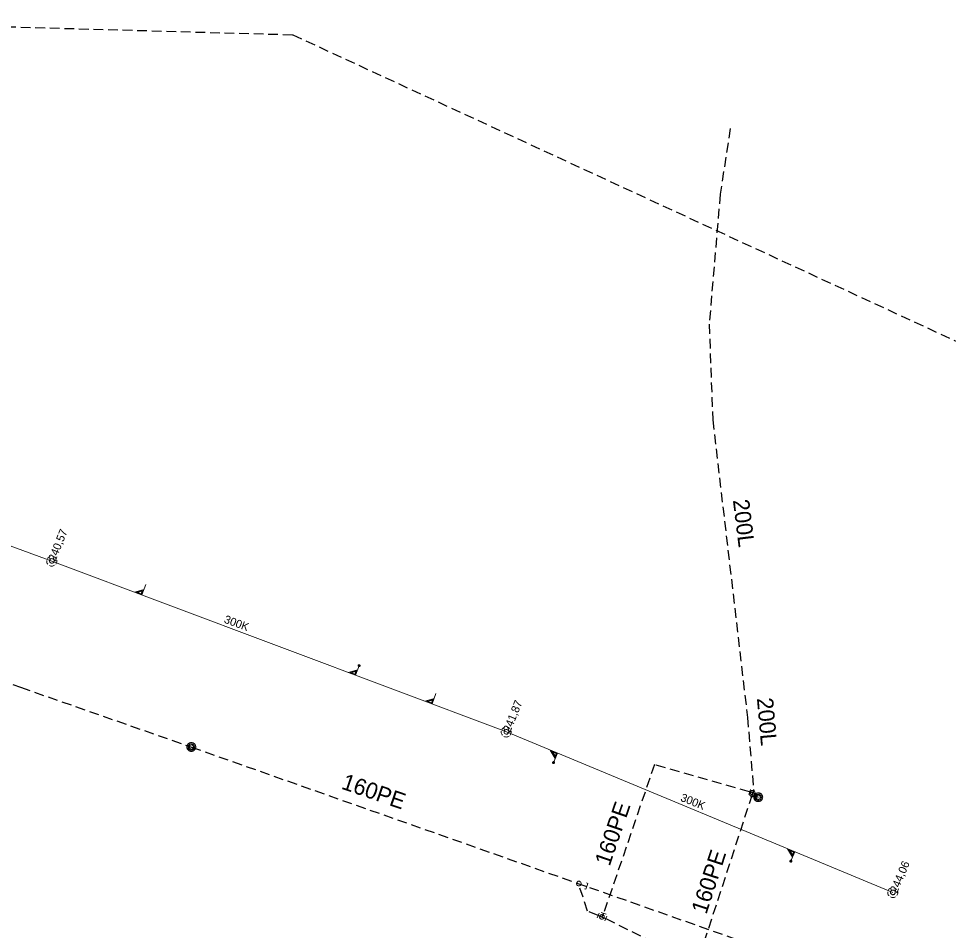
# Model space of a CAD drawing. Extents: x -735085 to -733500, y -1044153 to -1043402.
# Drawn here: x -734984.7 to -734892.7, y -1043524 to -1043433.9 of the extents above; entities that cross this region are included whole.
import ezdxf

# ---------------------------------------------------------------- set-up
doc = ezdxf.new("R2010")
doc.units = 0
doc.header["$LTSCALE"] = 0.32
doc.linetypes.add('MEDIUM_DASHED', pattern=[4.5, 3, -1.5])
doc.layers.add('15', color=7, linetype='Continuous')
doc.layers.add('16', color=7, linetype='Continuous')
for name, color, linetype, lineweight in [('18', 7, 'Continuous', 13), ('20', 7, 'Continuous', 13), ('63', 7, 'MEDIUM_DASHED', 25), ('8', 7, 'Continuous', 13)]:
    doc.layers.add(name, color=color, linetype=linetype, lineweight=lineweight)

msp = doc.modelspace()

# ---------------------------------------------------------------- linework, layer by layer
at = {"layer": '18'}
for points in [[(-734981.868, -1043487.429), (-734981.874, -1043487.506), (-734981.869, -1043487.583), (-734981.852, -1043487.658), (-734981.823, -1043487.729), (-734981.782, -1043487.795), (-734981.767, -1043487.817)], [(-734981.523, -1043487.037), (-734981.594, -1043487.065), (-734981.661, -1043487.104), (-734981.721, -1043487.152), (-734981.772, -1043487.209), (-734981.796, -1043487.243)], [(-734980.982, -1043487.22), (-734981.032, -1043487.162), (-734981.09, -1043487.112), (-734981.155, -1043487.071), (-734981.226, -1043487.042), (-734981.275, -1043487.028)], [(-734980.987, -1043487.806), (-734980.946, -1043487.741), (-734980.915, -1043487.671), (-734980.896, -1043487.596), (-734980.888, -1043487.52), (-734980.893, -1043487.443), (-734980.899, -1043487.408)], [(-734981.61, -1043487.946), (-734981.54, -1043487.977), (-734981.465, -1043487.996), (-734981.389, -1043488.003), (-734981.312, -1043487.998), (-734981.237, -1043487.981), (-734981.165, -1043487.953), (-734981.105, -1043487.918)], [(-734972.091, -1043489.814), (-734972.477, -1043490.84), (-734973.197, -1043490.569), (-734972.273, -1043490.299)], [(-734972.362, -1043490.392), (-734972.508, -1043490.781), (-734973.038, -1043490.582), (-734972.361, -1043490.391)], [(-734972.435, -1043490.454), (-734972.538, -1043490.726), (-734972.886, -1043490.595), (-734972.434, -1043490.454)], [(-734950.962, -1043497.749), (-734951.347, -1043498.774), (-734952.068, -1043498.503), (-734951.144, -1043498.233)], [(-734951.306, -1043498.388), (-734951.408, -1043498.661), (-734951.756, -1043498.53), (-734951.305, -1043498.388)], [(-734943.401, -1043500.593), (-734943.787, -1043501.619), (-734944.507, -1043501.348), (-734943.583, -1043501.078)], [(-734943.672, -1043501.171), (-734943.818, -1043501.56), (-734944.348, -1043501.361), (-734943.671, -1043501.17)], [(-734943.745, -1043501.233), (-734943.848, -1043501.505), (-734944.196, -1043501.374), (-734943.744, -1043501.233)], [(-734936.593, -1043503.917), (-734936.664, -1043503.945), (-734936.73, -1043503.984), (-734936.791, -1043504.032), (-734936.842, -1043504.089), (-734936.865, -1043504.123)], [(-734936.051, -1043504.1), (-734936.102, -1043504.042), (-734936.159, -1043503.992), (-734936.225, -1043503.951), (-734936.296, -1043503.922), (-734936.345, -1043503.908)], [(-734936.938, -1043504.309), (-734936.943, -1043504.386), (-734936.938, -1043504.463), (-734936.921, -1043504.538), (-734936.892, -1043504.609), (-734936.852, -1043504.675), (-734936.837, -1043504.697)], [(-734936.679, -1043504.826), (-734936.61, -1043504.857), (-734936.534, -1043504.876), (-734936.458, -1043504.883), (-734936.382, -1043504.878), (-734936.306, -1043504.861), (-734936.235, -1043504.833), (-734936.174, -1043504.798)], [(-734936.056, -1043504.686), (-734936.016, -1043504.621), (-734935.985, -1043504.551), (-734935.965, -1043504.476), (-734935.958, -1043504.4), (-734935.963, -1043504.323), (-734935.968, -1043504.288)], [(-734931.808, -1043507.489), (-734931.388, -1043506.478), (-734932.1, -1043506.182), (-734931.61, -1043507.011)], [(-734931.611, -1043506.882), (-734931.452, -1043506.498), (-734931.974, -1043506.281), (-734931.612, -1043506.884)], [(-734931.623, -1043506.787), (-734931.511, -1043506.518), (-734931.853, -1043506.375), (-734931.622, -1043506.788)], [(-734908.348, -1043517.226), (-734907.928, -1043516.215), (-734908.64, -1043515.919), (-734908.15, -1043516.748)], [(-734908.151, -1043516.619), (-734907.992, -1043516.235), (-734908.514, -1043516.018), (-734908.152, -1043516.621)], [(-734908.163, -1043516.524), (-734908.051, -1043516.255), (-734908.393, -1043516.112), (-734908.162, -1043516.525)], [(-734898.728, -1043520.169), (-734898.733, -1043520.246), (-734898.728, -1043520.323), (-734898.712, -1043520.398), (-734898.683, -1043520.469), (-734898.642, -1043520.535), (-734898.627, -1043520.557)], [(-734898.383, -1043519.777), (-734898.454, -1043519.805), (-734898.521, -1043519.844), (-734898.581, -1043519.892), (-734898.632, -1043519.949), (-734898.656, -1043519.983)], [(-734898.47, -1043520.686), (-734898.4, -1043520.717), (-734898.325, -1043520.736), (-734898.249, -1043520.743), (-734898.172, -1043520.738), (-734898.097, -1043520.721), (-734898.025, -1043520.693), (-734897.965, -1043520.658)], [(-734897.842, -1043519.96), (-734897.892, -1043519.902), (-734897.95, -1043519.852), (-734898.015, -1043519.811), (-734898.086, -1043519.782), (-734898.135, -1043519.768)], [(-734897.847, -1043520.546), (-734897.806, -1043520.481), (-734897.775, -1043520.411), (-734897.755, -1043520.336), (-734897.748, -1043520.26), (-734897.753, -1043520.183), (-734897.759, -1043520.148)]]:
    msp.add_lwpolyline(points, dxfattribs=at)
for points in [[(-734981.139, -1043487.489), (-734981.145, -1043487.437), (-734981.163, -1043487.387), (-734981.191, -1043487.343), (-734981.229, -1043487.306), (-734981.274, -1043487.279), (-734981.324, -1043487.263), (-734981.376, -1043487.258), (-734981.428, -1043487.265), (-734981.477, -1043487.284), (-734981.521, -1043487.314), (-734981.556, -1043487.353), (-734981.582, -1043487.398), (-734981.597, -1043487.449), (-734981.6, -1043487.501), (-734981.592, -1043487.553), (-734981.571, -1043487.601), (-734981.541, -1043487.644), (-734981.501, -1043487.679), (-734981.455, -1043487.703), (-734981.404, -1043487.717), (-734981.352, -1043487.719), (-734981.3, -1043487.709), (-734981.252, -1043487.687), (-734981.21, -1043487.655), (-734981.177, -1043487.615), (-734981.153, -1043487.568), (-734981.141, -1043487.517)], [(-734951.232, -1043498.325), (-734951.378, -1043498.715), (-734951.908, -1043498.516)], [(-734951.083, -1043497.804), (-734951.089, -1043497.837), (-734951.083, -1043497.87), (-734951.066, -1043497.898), (-734951.04, -1043497.919), (-734951.009, -1043497.93), (-734950.975, -1043497.928), (-734950.943, -1043497.916), (-734950.919, -1043497.893), (-734950.904, -1043497.863), (-734950.901, -1043497.83), (-734950.909, -1043497.797), (-734950.928, -1043497.77), (-734950.955, -1043497.751), (-734950.988, -1043497.742), (-734951.022, -1043497.745), (-734951.051, -1043497.761), (-734951.074, -1043497.786)], [(-734951.058, -1043497.814), (-734951.062, -1043497.842), (-734951.055, -1043497.869), (-734951.037, -1043497.89), (-734951.011, -1043497.903), (-734950.983, -1043497.904), (-734950.957, -1043497.892), (-734950.938, -1043497.872), (-734950.929, -1043497.845), (-734950.931, -1043497.818), (-734950.946, -1043497.793), (-734950.968, -1043497.776), (-734950.996, -1043497.77), (-734951.024, -1043497.777), (-734951.046, -1043497.793)], [(-734936.208, -1043504.369), (-734936.215, -1043504.317), (-734936.232, -1043504.267), (-734936.261, -1043504.223), (-734936.299, -1043504.186), (-734936.343, -1043504.159), (-734936.394, -1043504.143), (-734936.446, -1043504.138), (-734936.497, -1043504.145), (-734936.546, -1043504.164), (-734936.59, -1043504.194), (-734936.625, -1043504.233), (-734936.652, -1043504.278), (-734936.666, -1043504.329), (-734936.669, -1043504.381), (-734936.661, -1043504.433), (-734936.641, -1043504.481), (-734936.61, -1043504.524), (-734936.571, -1043504.559), (-734936.524, -1043504.583), (-734936.473, -1043504.597), (-734936.421, -1043504.599), (-734936.37, -1043504.589), (-734936.321, -1043504.567), (-734936.279, -1043504.535), (-734936.247, -1043504.495), (-734936.223, -1043504.448), (-734936.21, -1043504.397)], [(-734931.859, -1043507.366), (-734931.867, -1043507.398), (-734931.862, -1043507.432), (-734931.846, -1043507.461), (-734931.82, -1043507.483), (-734931.789, -1043507.494), (-734931.756, -1043507.494), (-734931.724, -1043507.482), (-734931.699, -1043507.461), (-734931.682, -1043507.432), (-734931.678, -1043507.398), (-734931.685, -1043507.365), (-734931.703, -1043507.338), (-734931.73, -1043507.318), (-734931.762, -1043507.308), (-734931.795, -1043507.31), (-734931.826, -1043507.324), (-734931.85, -1043507.348)], [(-734931.834, -1043507.374), (-734931.839, -1043507.402), (-734931.832, -1043507.43), (-734931.815, -1043507.452), (-734931.789, -1043507.465), (-734931.762, -1043507.467), (-734931.735, -1043507.457), (-734931.715, -1043507.437), (-734931.705, -1043507.41), (-734931.707, -1043507.382), (-734931.72, -1043507.358), (-734931.743, -1043507.339), (-734931.769, -1043507.333), (-734931.797, -1043507.338), (-734931.821, -1043507.354)], [(-734908.399, -1043517.103), (-734908.407, -1043517.135), (-734908.402, -1043517.169), (-734908.386, -1043517.198), (-734908.36, -1043517.22), (-734908.329, -1043517.231), (-734908.296, -1043517.231), (-734908.264, -1043517.219), (-734908.239, -1043517.198), (-734908.222, -1043517.169), (-734908.218, -1043517.135), (-734908.225, -1043517.102), (-734908.243, -1043517.075), (-734908.27, -1043517.055), (-734908.302, -1043517.045), (-734908.335, -1043517.047), (-734908.366, -1043517.061), (-734908.39, -1043517.085)], [(-734908.374, -1043517.111), (-734908.379, -1043517.139), (-734908.372, -1043517.167), (-734908.355, -1043517.189), (-734908.329, -1043517.202), (-734908.302, -1043517.204), (-734908.275, -1043517.194), (-734908.255, -1043517.174), (-734908.245, -1043517.147), (-734908.247, -1043517.119), (-734908.26, -1043517.095), (-734908.283, -1043517.076), (-734908.309, -1043517.07), (-734908.337, -1043517.075), (-734908.361, -1043517.091)], [(-734897.999, -1043520.229), (-734898.005, -1043520.177), (-734898.022, -1043520.127), (-734898.051, -1043520.083), (-734898.089, -1043520.046), (-734898.134, -1043520.019), (-734898.184, -1043520.003), (-734898.236, -1043519.998), (-734898.288, -1043520.005), (-734898.337, -1043520.024), (-734898.38, -1043520.054), (-734898.416, -1043520.093), (-734898.442, -1043520.138), (-734898.456, -1043520.189), (-734898.46, -1043520.241), (-734898.451, -1043520.293), (-734898.431, -1043520.341), (-734898.401, -1043520.384), (-734898.361, -1043520.419), (-734898.315, -1043520.443), (-734898.264, -1043520.457), (-734898.212, -1043520.459), (-734898.16, -1043520.449), (-734898.112, -1043520.427), (-734898.07, -1043520.395), (-734898.037, -1043520.355), (-734898.013, -1043520.308), (-734898, -1043520.257)]]:
    msp.add_lwpolyline(points, close=True, dxfattribs=at)
at = {"layer": '20'}
msp.add_line((-734898.23, -1043520.24), (-734936.44, -1043504.38), dxfattribs=at)
msp.add_line((-734898.23, -1043520.24), (-734936.44, -1043504.38), dxfattribs=at)
msp.add_lwpolyline([(-734936.44, -1043504.38), (-734981.37, -1043487.5), (-735028.8, -1043470.1)], dxfattribs=at)
msp.add_lwpolyline([(-734936.44, -1043504.38), (-734981.37, -1043487.5), (-735028.8, -1043470.1)], dxfattribs=at)
at = {"layer": '63'}
msp.add_lwpolyline([(-734796.022, -1043808.279), (-734957.658, -1043641.023), (-734957.66, -1043641.021), (-735032.487, -1043496.398), (-735032.488, -1043496.396), (-735032.488, -1043496.394), (-735032.488, -1043496.393), (-735032.488, -1043496.391), (-735014.686, -1043433.916), (-735014.686, -1043433.914), (-735014.685, -1043433.913), (-735014.683, -1043433.911), (-735014.682, -1043433.91), (-735014.68, -1043433.909), (-735014.678, -1043433.909), (-735014.676, -1043433.909), (-734957.569, -1043435.5), (-734957.567, -1043435.5), (-734957.565, -1043435.501), (-734250.468, -1043761.931)], dxfattribs=at)
at = {"layer": '8', "linetype": 'MEDIUM_DASHED', "lineweight": 25}
for p, q in [((-734967.581, -1043505.873), (-734929.271, -1043519.373)), ((-734912.085, -1043510.397), (-734912.138, -1043510.559)), ((-734912.138, -1043510.559), (-734917.559, -1043527.16)), ((-734929.271, -1043519.373), (-734928.487, -1043519.649)), ((-734926.989, -1043522.67), (-734926.609, -1043522.81)), ((-734926.609, -1043522.81), (-734917.614, -1043527.33))]:
    msp.add_line(p, q, dxfattribs=at)
at = {"layer": '8'}
for p, q in [((-734912.317, -1043510.059), (-734912.459, -1043510.556)), ((-734911.778, -1043510.402), (-734911.938, -1043510.893)), ((-734927.261, -1043522.278), (-734927.457, -1043522.757)), ((-734927.075, -1043522.215), (-734926.586, -1043522.383)), ((-734926.519, -1043522.565), (-734926.698, -1043523.05))]:
    msp.add_line(p, q, dxfattribs=at)
at = {"layer": '8', "lineweight": 25}
for p, q in [((-734912.085, -1043510.397), (-734912.39, -1043510.31)), ((-734912.138, -1043510.559), (-734911.859, -1043510.65)), ((-734911.859, -1043510.65), (-734911.53, -1043510.84))]:
    msp.add_line(p, q, dxfattribs=at)
at = {"layer": '8', "linetype": 'MEDIUM_DASHED', "lineweight": 25}
for points in [[(-734914.3, -1043444.76), (-734915.3, -1043451.26), (-734916.39, -1043464.1), (-734916.039, -1043473.56), (-734912.6, -1043502.95), (-734912.002, -1043510.076), (-734912.085, -1043510.397)], [(-735085.256, -1043462.997), (-734984.456, -1043499.972), (-734967.581, -1043505.873)], [(-734912.39, -1043510.31), (-734921.8, -1043507.6), (-734926.829, -1043522.3)], [(-734927.36, -1043522.519), (-734928.41, -1043522.08), (-734929.289, -1043519.424), (-734929.271, -1043519.373)], [(-734928.23, -1043519.739), (-734905.133, -1043527.879), (-734903.548, -1043528.837), (-734842.335, -1043550.559)], [(-734926.829, -1043522.3), (-734926.989, -1043522.67), (-734927.36, -1043522.519)]]:
    msp.add_lwpolyline(points, dxfattribs=at)
at = {"layer": '8'}
for points in [[(-734967.149, -1043505.861), (-734967.152, -1043505.816), (-734967.159, -1043505.771), (-734967.171, -1043505.726), (-734967.186, -1043505.684), (-734967.208, -1043505.643), (-734967.233, -1043505.604), (-734967.262, -1043505.569), (-734967.294, -1043505.536), (-734967.33, -1043505.508), (-734967.367, -1043505.483), (-734967.409, -1043505.462), (-734967.451, -1043505.445), (-734967.495, -1043505.433), (-734967.541, -1043505.426), (-734967.587, -1043505.424), (-734967.632, -1043505.426), (-734967.678, -1043505.433), (-734967.722, -1043505.445), (-734967.765, -1043505.462), (-734967.806, -1043505.483), (-734967.843, -1043505.508), (-734967.88, -1043505.536), (-734967.912, -1043505.569), (-734967.941, -1043505.604), (-734967.966, -1043505.643), (-734967.987, -1043505.684), (-734968.002, -1043505.726), (-734968.015, -1043505.771), (-734968.022, -1043505.816), (-734968.024, -1043505.862), (-734968.022, -1043505.907), (-734968.015, -1043505.952), (-734968.002, -1043505.997), (-734967.987, -1043506.039), (-734967.966, -1043506.08), (-734967.941, -1043506.119), (-734967.912, -1043506.154), (-734967.88, -1043506.187), (-734967.843, -1043506.215), (-734967.806, -1043506.24), (-734967.765, -1043506.261), (-734967.722, -1043506.278), (-734967.678, -1043506.289), (-734967.632, -1043506.297), (-734967.587, -1043506.299), (-734967.541, -1043506.297), (-734967.495, -1043506.289), (-734967.451, -1043506.278), (-734967.409, -1043506.261), (-734967.367, -1043506.24), (-734967.33, -1043506.215), (-734967.294, -1043506.187), (-734967.262, -1043506.154), (-734967.233, -1043506.119), (-734967.208, -1043506.08), (-734967.186, -1043506.039), (-734967.171, -1043505.997), (-734967.159, -1043505.952), (-734967.152, -1043505.907), (-734967.149, -1043505.862)], [(-734911.1, -1043510.829), (-734911.102, -1043510.784), (-734911.109, -1043510.739), (-734911.121, -1043510.694), (-734911.137, -1043510.652), (-734911.158, -1043510.611), (-734911.183, -1043510.572), (-734911.212, -1043510.537), (-734911.244, -1043510.504), (-734911.28, -1043510.476), (-734911.318, -1043510.451), (-734911.359, -1043510.43), (-734911.402, -1043510.413), (-734911.446, -1043510.401), (-734911.491, -1043510.394), (-734911.537, -1043510.392), (-734911.583, -1043510.394), (-734911.628, -1043510.401), (-734911.672, -1043510.413), (-734911.715, -1043510.43), (-734911.756, -1043510.451), (-734911.794, -1043510.476), (-734911.83, -1043510.504), (-734911.862, -1043510.537), (-734911.891, -1043510.572), (-734911.916, -1043510.611), (-734911.937, -1043510.652), (-734911.953, -1043510.694), (-734911.965, -1043510.739), (-734911.972, -1043510.784), (-734911.975, -1043510.83), (-734911.972, -1043510.875), (-734911.965, -1043510.92), (-734911.953, -1043510.965), (-734911.937, -1043511.007), (-734911.916, -1043511.048), (-734911.891, -1043511.087), (-734911.862, -1043511.122), (-734911.83, -1043511.155), (-734911.794, -1043511.183), (-734911.756, -1043511.208), (-734911.715, -1043511.229), (-734911.672, -1043511.246), (-734911.628, -1043511.257), (-734911.583, -1043511.265), (-734911.537, -1043511.267), (-734911.491, -1043511.265), (-734911.446, -1043511.257), (-734911.402, -1043511.246), (-734911.359, -1043511.229), (-734911.318, -1043511.208), (-734911.28, -1043511.183), (-734911.244, -1043511.155), (-734911.212, -1043511.122), (-734911.183, -1043511.087), (-734911.158, -1043511.048), (-734911.137, -1043511.007), (-734911.121, -1043510.965), (-734911.109, -1043510.92), (-734911.102, -1043510.875), (-734911.1, -1043510.83)], [(-734928.526, -1043519.304), (-734928.38, -1043519.356), (-734928.581, -1043519.928), (-734928.727, -1043519.877)]]:
    msp.add_lwpolyline(points, dxfattribs=at)
for points in [[(-734967.262, -1043505.869), (-734967.269, -1043505.808), (-734967.287, -1043505.748), (-734967.316, -1043505.693), (-734967.355, -1043505.645), (-734967.402, -1043505.605), (-734967.456, -1043505.575), (-734967.515, -1043505.555), (-734967.576, -1043505.548), (-734967.639, -1043505.552), (-734967.698, -1043505.568), (-734967.754, -1043505.596), (-734967.804, -1043505.633), (-734967.845, -1043505.68), (-734967.877, -1043505.733), (-734967.897, -1043505.792), (-734967.907, -1043505.853), (-734967.904, -1043505.915), (-734967.889, -1043505.975), (-734967.863, -1043506.032), (-734967.826, -1043506.082), (-734967.781, -1043506.125), (-734967.728, -1043506.157), (-734967.671, -1043506.18), (-734967.61, -1043506.19), (-734967.548, -1043506.189), (-734967.487, -1043506.176), (-734967.429, -1043506.151), (-734967.379, -1043506.116), (-734967.335, -1043506.072), (-734967.301, -1043506.02), (-734967.277, -1043505.963), (-734967.265, -1043505.902)], [(-734967.377, -1043505.869), (-734967.382, -1043505.82), (-734967.399, -1043505.773), (-734967.428, -1043505.732), (-734967.466, -1043505.699), (-734967.51, -1043505.675), (-734967.558, -1043505.663), (-734967.608, -1043505.662), (-734967.656, -1043505.674), (-734967.701, -1043505.696), (-734967.739, -1043505.729), (-734967.767, -1043505.769), (-734967.787, -1043505.816), (-734967.794, -1043505.865), (-734967.789, -1043505.915), (-734967.772, -1043505.962), (-734967.745, -1043506.004), (-734967.708, -1043506.038), (-734967.664, -1043506.062), (-734967.617, -1043506.076), (-734967.566, -1043506.077), (-734967.517, -1043506.067), (-734967.473, -1043506.045), (-734967.434, -1043506.013), (-734967.404, -1043505.974), (-734967.385, -1043505.928), (-734967.377, -1043505.878)], [(-734911.907, -1043510.548), (-734911.913, -1043510.496), (-734911.931, -1043510.446), (-734911.959, -1043510.402), (-734911.997, -1043510.365), (-734912.042, -1043510.338), (-734912.092, -1043510.322), (-734912.144, -1043510.317), (-734912.196, -1043510.324), (-734912.245, -1043510.343), (-734912.289, -1043510.373), (-734912.324, -1043510.412), (-734912.35, -1043510.457), (-734912.365, -1043510.508), (-734912.368, -1043510.56), (-734912.36, -1043510.612), (-734912.339, -1043510.66), (-734912.309, -1043510.703), (-734912.269, -1043510.738), (-734912.223, -1043510.762), (-734912.172, -1043510.776), (-734912.12, -1043510.778), (-734912.068, -1043510.768), (-734912.02, -1043510.746), (-734911.978, -1043510.714), (-734911.945, -1043510.674), (-734911.921, -1043510.627), (-734911.909, -1043510.576)], [(-734911.853, -1043510.386), (-734911.86, -1043510.334), (-734911.877, -1043510.284), (-734911.906, -1043510.24), (-734911.944, -1043510.203), (-734911.989, -1043510.176), (-734912.039, -1043510.16), (-734912.091, -1043510.155), (-734912.142, -1043510.162), (-734912.191, -1043510.181), (-734912.235, -1043510.211), (-734912.271, -1043510.25), (-734912.297, -1043510.295), (-734912.311, -1043510.346), (-734912.315, -1043510.398), (-734912.306, -1043510.45), (-734912.286, -1043510.498), (-734912.255, -1043510.541), (-734912.216, -1043510.576), (-734912.169, -1043510.6), (-734912.119, -1043510.614), (-734912.066, -1043510.616), (-734912.015, -1043510.606), (-734911.967, -1043510.584), (-734911.924, -1043510.552), (-734911.892, -1043510.512), (-734911.868, -1043510.465), (-734911.855, -1043510.414)], [(-734911.213, -1043510.837), (-734911.219, -1043510.776), (-734911.237, -1043510.716), (-734911.266, -1043510.661), (-734911.305, -1043510.613), (-734911.352, -1043510.573), (-734911.406, -1043510.543), (-734911.465, -1043510.523), (-734911.527, -1043510.516), (-734911.589, -1043510.52), (-734911.649, -1043510.536), (-734911.704, -1043510.564), (-734911.754, -1043510.601), (-734911.795, -1043510.648), (-734911.827, -1043510.701), (-734911.847, -1043510.76), (-734911.857, -1043510.821), (-734911.854, -1043510.883), (-734911.839, -1043510.943), (-734911.813, -1043511), (-734911.777, -1043511.05), (-734911.731, -1043511.093), (-734911.679, -1043511.125), (-734911.621, -1043511.148), (-734911.56, -1043511.158), (-734911.498, -1043511.157), (-734911.437, -1043511.144), (-734911.38, -1043511.119), (-734911.329, -1043511.084), (-734911.285, -1043511.04), (-734911.251, -1043510.988), (-734911.227, -1043510.931), (-734911.215, -1043510.87)], [(-734911.327, -1043510.837), (-734911.333, -1043510.788), (-734911.35, -1043510.741), (-734911.378, -1043510.7), (-734911.416, -1043510.667), (-734911.46, -1043510.643), (-734911.508, -1043510.631), (-734911.558, -1043510.63), (-734911.606, -1043510.642), (-734911.651, -1043510.664), (-734911.689, -1043510.697), (-734911.718, -1043510.737), (-734911.737, -1043510.784), (-734911.744, -1043510.833), (-734911.739, -1043510.883), (-734911.722, -1043510.93), (-734911.695, -1043510.972), (-734911.658, -1043511.006), (-734911.615, -1043511.03), (-734911.567, -1043511.044), (-734911.517, -1043511.045), (-734911.468, -1043511.035), (-734911.423, -1043511.013), (-734911.384, -1043510.981), (-734911.354, -1043510.942), (-734911.335, -1043510.896), (-734911.327, -1043510.846)], [(-734929.039, -1043519.362), (-734929.045, -1043519.31), (-734929.063, -1043519.26), (-734929.091, -1043519.216), (-734929.129, -1043519.179), (-734929.174, -1043519.152), (-734929.224, -1043519.136), (-734929.276, -1043519.131), (-734929.328, -1043519.138), (-734929.377, -1043519.157), (-734929.421, -1043519.187), (-734929.456, -1043519.226), (-734929.482, -1043519.271), (-734929.497, -1043519.322), (-734929.5, -1043519.374), (-734929.492, -1043519.426), (-734929.471, -1043519.474), (-734929.441, -1043519.517), (-734929.401, -1043519.552), (-734929.355, -1043519.576), (-734929.304, -1043519.59), (-734929.252, -1043519.592), (-734929.2, -1043519.582), (-734929.152, -1043519.56), (-734929.11, -1043519.528), (-734929.077, -1043519.488), (-734929.053, -1043519.441), (-734929.041, -1043519.39)], [(-734926.757, -1043522.659), (-734926.764, -1043522.607), (-734926.781, -1043522.557), (-734926.809, -1043522.513), (-734926.848, -1043522.476), (-734926.892, -1043522.449), (-734926.943, -1043522.433), (-734926.995, -1043522.428), (-734927.046, -1043522.435), (-734927.095, -1043522.454), (-734927.139, -1043522.484), (-734927.174, -1043522.523), (-734927.201, -1043522.568), (-734927.215, -1043522.619), (-734927.218, -1043522.671), (-734927.21, -1043522.723), (-734927.19, -1043522.771), (-734927.159, -1043522.814), (-734927.12, -1043522.849), (-734927.073, -1043522.873), (-734927.022, -1043522.887), (-734926.97, -1043522.889), (-734926.919, -1043522.879), (-734926.87, -1043522.857), (-734926.828, -1043522.825), (-734926.796, -1043522.785), (-734926.772, -1043522.738), (-734926.759, -1043522.687)]]:
    msp.add_lwpolyline(points, close=True, dxfattribs=at)

# ---------------------------------------------------------------- texts
at = {"layer": '15'}
for s, rotation, p in [('200L', 277, (-734914.047, -1043481.485)), ('200L', 275, (-734911.672, -1043501.061)), ('160PE ', 341, (-734952.834, -1043509.967)), ('160PE ', 71, (-734926.233, -1043517.708)), ('160PE ', 72, (-734916.67, -1043522.471))]:
    msp.add_text(s, height=1.6, rotation=rotation, dxfattribs=at).set_placement(p)
at = {"layer": '16'}
for s, rotation, p in [('240,57', 68, (-734981.026, -1043487.586)), ('300K', 340, (-734964.416, -1043493.572)), ('241,87', 68, (-734936.062, -1043504.491)), ('300K', 338, (-734919.297, -1043511.165)), ('244,06', 67, (-734897.821, -1043520.36))]:
    msp.add_text(s, height=0.8, rotation=rotation, dxfattribs=at).set_placement(p)

doc.saveas('drawing.dxf')
